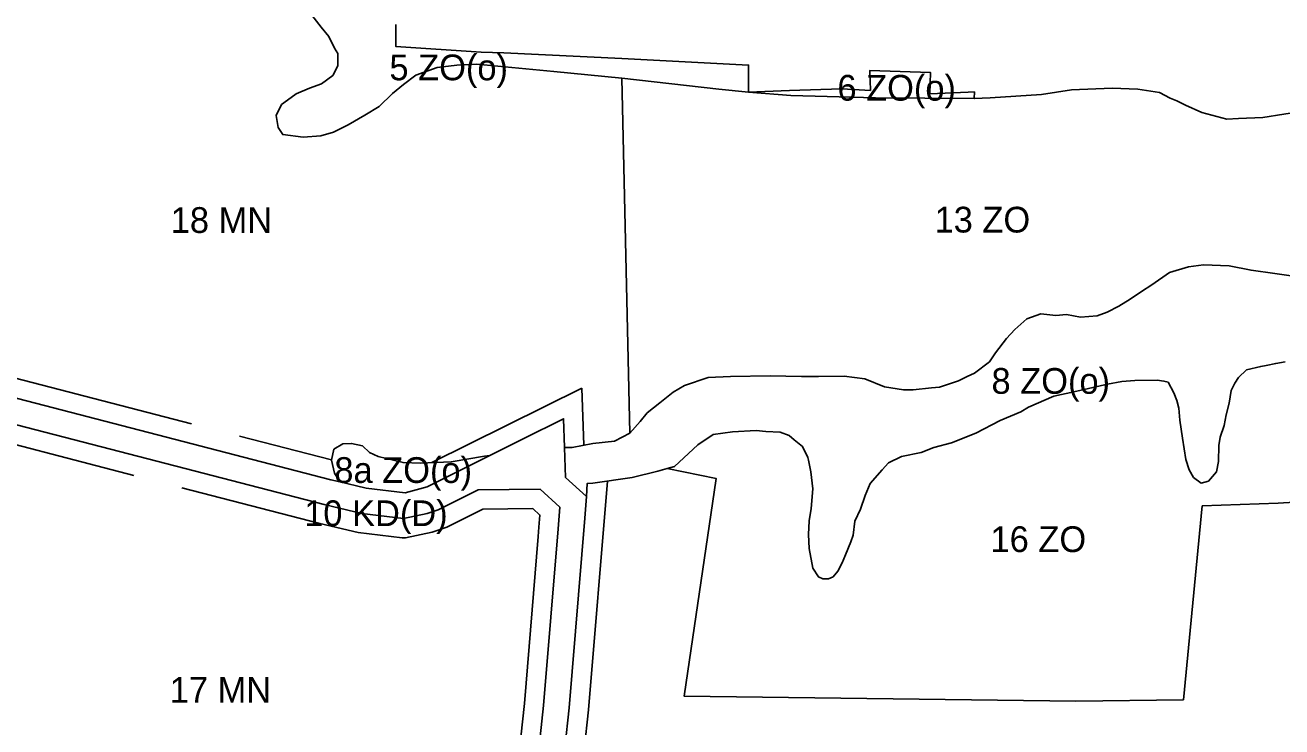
# Model space of a CAD drawing. Extents: x 7418056 to 7420315, y 5537846 to 5539505.
# Drawn here: x 7419326.3 to 7419814.6, y 5538625.8 to 5538898.4 of the extents above; entities that cross this region are included whole.
import ezdxf

# ---------------------------------------------------------------- set-up
doc = ezdxf.new("R2010")
doc.units = 0
for name, color, linetype in [('linie_rozgraniczajace', 7, 'Continuous'), ('linie_zabudowy_nieprzekraczalne', 7, 'Continuous'), ('oznaczenia_przeznaczen', 7, 'Continuous')]:
    doc.layers.add(name, color=color, linetype=linetype)

msp = doc.modelspace()

# ---------------------------------------------------------------- linework, layer by layer
at = {"layer": 'linie_rozgraniczajace'}
for points in [[(7419435.41, 5538905.24), (7419441.34, 5538897.54), (7419444.29, 5538893.92), (7419446.58, 5538889.34), (7419447.86, 5538887.27), (7419447.85, 5538882.53), (7419445.84, 5538878.78), (7419441.44, 5538875.59), (7419436.77, 5538873.9), (7419431.63, 5538871.68), (7419428.22, 5538869.21), (7419425.96, 5538867.48), (7419423.84, 5538863.25), (7419424.68, 5538858.55), (7419426.43, 5538855.82), (7419434.31, 5538854.85), (7419441.18, 5538855.33), (7419446.09, 5538856.82), (7419451.79, 5538859.64), (7419458.32, 5538863.36), (7419463.87, 5538866.68), (7419469.04, 5538871.8), (7419473.34, 5538875.24), (7419478.09, 5538878.94), (7419486.4, 5538881.85), (7419494.11, 5538882.81), (7419501.82, 5538883.13), (7419531.77, 5538880.4), (7419558.13, 5538877.75), (7419561.27, 5538739.79), (7419555.26, 5538736.69), (7419546.94, 5538735.83), (7419538.84, 5538734.29), (7419535.92, 5538734.26), (7419535.54, 5538745.43), (7419519.86, 5538737.62), (7419506.87, 5538731.17), (7419504.79, 5538730.89), (7419491.89, 5538728.69), (7419479.76, 5538728.2), (7419473.2, 5538728.4), (7419463.51, 5538730.81), (7419460.18, 5538732.31), (7419457.41, 5538734.97), (7419453.2, 5538735.84), (7419449.73, 5538735.7), (7419446.34, 5538733.62), (7419445.34, 5538729.38), (7419446.48, 5538724.28), (7419447.98, 5538722.01), (7419448.08, 5538721.04), (7419445.05, 5538721.75), (7419299.76, 5538759.34)], [(7419470.33, 5538898.55), (7419470.4, 5538890.01), (7419503.49, 5538887.91), (7419512.32, 5538887.58), (7419558.18, 5538885.41), (7419607.4, 5538882.82), (7419607.39, 5538872.31), (7419595.87, 5538873.47), (7419558.13, 5538877.75), (7419531.77, 5538880.4), (7419501.82, 5538883.13), (7419494.11, 5538882.81), (7419486.4, 5538881.85), (7419478.09, 5538878.94), (7419473.34, 5538875.24), (7419469.04, 5538871.8), (7419463.87, 5538866.68), (7419458.32, 5538863.36), (7419451.79, 5538859.64), (7419446.09, 5538856.82), (7419441.18, 5538855.33), (7419434.31, 5538854.85), (7419426.43, 5538855.82), (7419424.68, 5538858.55), (7419423.84, 5538863.25), (7419425.96, 5538867.48), (7419428.22, 5538869.21), (7419431.63, 5538871.68), (7419436.77, 5538873.9), (7419441.44, 5538875.59), (7419445.84, 5538878.78), (7419447.85, 5538882.53), (7419447.86, 5538887.27), (7419446.58, 5538889.34), (7419444.29, 5538893.92), (7419441.34, 5538897.54), (7419435.41, 5538905.24)], [(7419820.03, 5538800.76), (7419811.8, 5538801.83), (7419802.63, 5538803.1), (7419794.05, 5538804.8), (7419784.13, 5538805.26), (7419778.25, 5538804.5), (7419770.87, 5538802.29), (7419764.11, 5538797.5), (7419760.05, 5538794.9), (7419755.65, 5538791.95), (7419751.25, 5538789.17), (7419746.77, 5538786.8), (7419742.89, 5538785.36), (7419736.3, 5538784.91), (7419730.92, 5538785.91), (7419726.72, 5538785.51), (7419720.96, 5538786.2), (7419715.47, 5538784.25), (7419710.78, 5538780.06), (7419707.61, 5538776.63), (7419703.33, 5538771.07), (7419700.99, 5538767.61), (7419695.13, 5538763.2), (7419692.37, 5538761.92), (7419688.94, 5538760.15), (7419681.55, 5538757.74), (7419678.52, 5538757.39), (7419671.31, 5538756.62), (7419667.56, 5538756.71), (7419660.27, 5538757.82), (7419652.52, 5538760.97), (7419644.48, 5538762.04), (7419634.59, 5538761.81), (7419627.98, 5538761.89), (7419615.8, 5538762.1), (7419600.35, 5538761.81), (7419591.68, 5538761.46), (7419582.48, 5538758.34), (7419578.14, 5538755.83), (7419572.96, 5538751.67), (7419567.94, 5538747.7), (7419565.27, 5538744.33), (7419561.27, 5538739.79), (7419558.13, 5538877.75), (7419595.87, 5538873.47), (7419607.39, 5538872.31), (7419607.4, 5538872.31), (7419623.8, 5538871.02), (7419656.72, 5538870.12), (7419695.08, 5538869.84), (7419701.24, 5538870.09), (7419721.14, 5538871.44), (7419732.86, 5538873.18), (7419748.61, 5538873.82), (7419758.59, 5538873.53), (7419766.99, 5538872.21), (7419771.25, 5538870.03), (7419773.81, 5538868.91), (7419777.11, 5538867.31), (7419783.53, 5538864.42), (7419793.16, 5538861.82), (7419797.76, 5538862.07), (7419807.13, 5538862.49), (7419823.48, 5538865.05)], [(7419536.32, 5538722.59), (7419535.92, 5538734.26), (7419538.84, 5538734.29), (7419546.94, 5538735.83), (7419555.26, 5538736.69), (7419561.27, 5538739.79), (7419565.27, 5538744.33), (7419567.94, 5538747.7), (7419572.96, 5538751.67), (7419578.14, 5538755.83), (7419582.48, 5538758.34), (7419591.68, 5538761.46), (7419600.35, 5538761.81), (7419615.8, 5538762.1), (7419627.98, 5538761.89), (7419634.59, 5538761.81), (7419644.48, 5538762.04), (7419652.52, 5538760.97), (7419660.27, 5538757.82), (7419667.56, 5538756.71), (7419671.31, 5538756.62), (7419678.52, 5538757.39), (7419681.55, 5538757.74), (7419688.94, 5538760.15), (7419692.37, 5538761.92), (7419695.13, 5538763.2), (7419700.99, 5538767.61), (7419703.33, 5538771.07), (7419707.61, 5538776.63), (7419710.78, 5538780.06), (7419715.47, 5538784.25), (7419720.96, 5538786.2), (7419726.72, 5538785.51), (7419730.92, 5538785.91), (7419736.3, 5538784.91), (7419742.89, 5538785.36), (7419746.77, 5538786.8), (7419751.25, 5538789.17), (7419755.65, 5538791.95), (7419760.05, 5538794.9), (7419764.11, 5538797.5), (7419770.87, 5538802.29), (7419778.25, 5538804.5), (7419784.13, 5538805.26), (7419794.05, 5538804.8), (7419802.63, 5538803.1), (7419811.8, 5538801.83), (7419820.03, 5538800.76)], [(7419870.81, 5538716.16), (7419813.18, 5538712.6), (7419783.62, 5538711.58), (7419776.36, 5538636.3), (7419734.58, 5538635.75), (7419582.32, 5538637.71), (7419594.85, 5538722.21), (7419575.72, 5538726.07), (7419578.66, 5538726.9), (7419587.7, 5538735.25), (7419593.62, 5538739.31), (7419601.22, 5538740.32), (7419610.41, 5538740.86), (7419614.08, 5538740.49), (7419619.65, 5538740.2), (7419623.18, 5538738.95), (7419625.16, 5538737.3), (7419628.36, 5538734.69), (7419630.41, 5538730.33), (7419630.68, 5538729.41), (7419631.57, 5538724.78), (7419632.3, 5538718.26), (7419631.68, 5538710.53), (7419630.94, 5538705.83), (7419630.68, 5538700.44), (7419630.9, 5538695.08), (7419632.38, 5538687.43), (7419634.62, 5538684.01), (7419636.3, 5538683.2), (7419638.4, 5538683.23), (7419640.24, 5538684.01), (7419642.09, 5538686.2), (7419643.76, 5538689.52), (7419645.03, 5538692.61), (7419647.17, 5538697.61), (7419648, 5538700.21), (7419648.71, 5538705.61), (7419650.86, 5538710.37), (7419652.75, 5538715.59), (7419654.67, 5538720.34), (7419659.35, 5538725.66), (7419661.82, 5538728.34), (7419666.86, 5538730.79), (7419674.45, 5538732.32), (7419679.41, 5538734.25), (7419686.28, 5538736.09), (7419695.69, 5538739.78), (7419705.11, 5538744.82), (7419713.15, 5538748.18), (7419716.12, 5538749.94), (7419726.04, 5538754.21), (7419733.78, 5538755.91), (7419746.8, 5538758.94), (7419752.38, 5538759.86), (7419757.5, 5538760.3), (7419766.16, 5538760.42), (7419768.74, 5538760.06), (7419770.39, 5538759.66), (7419772.66, 5538755.54), (7419773.72, 5538752.55), (7419774.54, 5538749.55), (7419774.96, 5538744.89), (7419775.95, 5538737.92), (7419777.23, 5538729.56), (7419778.56, 5538725.65), (7419780.31, 5538722.68), (7419783.21, 5538720.46), (7419786.04, 5538721.22), (7419789.2, 5538724.82), (7419789.91, 5538728.85), (7419790.1, 5538735), (7419790.66, 5538738.28), (7419792.12, 5538742.78), (7419792.88, 5538747.02), (7419794.1, 5538751.51), (7419794.84, 5538756.44), (7419796.36, 5538759.31), (7419797.68, 5538761.46), (7419800.83, 5538764.39), (7419806.38, 5538765.79), (7419808.48, 5538766.12), (7419812.18, 5538766.97), (7419815.9, 5538767.58)], [(7419815.9, 5538767.58), (7419812.18, 5538766.97), (7419808.48, 5538766.12), (7419806.38, 5538765.79), (7419800.83, 5538764.39), (7419797.68, 5538761.46), (7419796.36, 5538759.31), (7419794.84, 5538756.44), (7419794.1, 5538751.51), (7419792.88, 5538747.02), (7419792.12, 5538742.78), (7419790.66, 5538738.28), (7419790.1, 5538735), (7419789.91, 5538728.85), (7419789.2, 5538724.82), (7419786.04, 5538721.22), (7419783.21, 5538720.46), (7419780.31, 5538722.68), (7419778.56, 5538725.65), (7419777.23, 5538729.56), (7419775.95, 5538737.92), (7419774.96, 5538744.89), (7419774.54, 5538749.55), (7419773.72, 5538752.55), (7419772.66, 5538755.54), (7419770.39, 5538759.66), (7419768.74, 5538760.06), (7419766.16, 5538760.42), (7419757.5, 5538760.3), (7419752.38, 5538759.86), (7419746.8, 5538758.94), (7419733.78, 5538755.91), (7419726.04, 5538754.21), (7419716.12, 5538749.94), (7419713.15, 5538748.18), (7419705.11, 5538744.82)], [(7419299.76, 5538759.34), (7419445.05, 5538721.75), (7419448.08, 5538721.04), (7419458.86, 5538718.51), (7419474.03, 5538716.65), (7419482.48, 5538719.05), (7419506.87, 5538731.17), (7419519.86, 5538737.62), (7419535.54, 5538745.43), (7419535.92, 5538734.26), (7419536.32, 5538722.59), (7419544.39, 5538715.22), (7419543.82, 5538706.76), (7419537.73, 5538633.12), (7419531.03, 5538570.98)], [(7419297.9, 5538749.52), (7419442.55, 5538712.07), (7419445.79, 5538711.3), (7419457.11, 5538708.65), (7419473.33, 5538706.66), (7419482.55, 5538708.68), (7419486.79, 5538710.03), (7419502.41, 5538717.79), (7419526.45, 5538718.07), (7419534.1, 5538711.07), (7419533.42, 5538702.73), (7419527.79, 5538634.11), (7419521.09, 5538572.08)], [(7419521.09, 5538572.08), (7419527.79, 5538634.11), (7419533.42, 5538702.73), (7419534.1, 5538711.07), (7419526.45, 5538718.07), (7419502.41, 5538717.79), (7419486.79, 5538710.03), (7419482.55, 5538708.68), (7419473.33, 5538706.66), (7419457.11, 5538708.65), (7419445.79, 5538711.3), (7419442.55, 5538712.07), (7419297.9, 5538749.52)], [(7419705.11, 5538744.82), (7419695.69, 5538739.78), (7419686.28, 5538736.09), (7419679.41, 5538734.25), (7419674.45, 5538732.32), (7419666.86, 5538730.79), (7419661.82, 5538728.34), (7419659.35, 5538725.66), (7419654.67, 5538720.34), (7419652.75, 5538715.59), (7419650.86, 5538710.37), (7419648.71, 5538705.61), (7419648, 5538700.21), (7419647.17, 5538697.61), (7419645.03, 5538692.61), (7419643.76, 5538689.52), (7419642.09, 5538686.2), (7419640.24, 5538684.01), (7419638.4, 5538683.23), (7419636.3, 5538683.2), (7419634.62, 5538684.01), (7419632.38, 5538687.43), (7419630.9, 5538695.08), (7419630.68, 5538700.44), (7419630.94, 5538705.83), (7419631.68, 5538710.53), (7419632.3, 5538718.26), (7419631.57, 5538724.78), (7419630.68, 5538729.41), (7419630.41, 5538730.33), (7419628.36, 5538734.69), (7419625.16, 5538737.3), (7419623.18, 5538738.95), (7419619.65, 5538740.2), (7419614.08, 5538740.49), (7419610.41, 5538740.86), (7419601.22, 5538740.32), (7419593.62, 5538739.31), (7419587.7, 5538735.25), (7419578.66, 5538726.9), (7419575.72, 5538726.07), (7419572.13, 5538725.07), (7419562.15, 5538722.58), (7419546.88, 5538720.38), (7419544.73, 5538720.32), (7419544.39, 5538715.22), (7419536.32, 5538722.59)], [(7419531.03, 5538570.98), (7419537.73, 5538633.12), (7419543.82, 5538706.76), (7419544.39, 5538715.22), (7419544.73, 5538720.32), (7419546.88, 5538720.38), (7419562.15, 5538722.58), (7419572.13, 5538725.07), (7419575.72, 5538726.07), (7419594.85, 5538722.21), (7419582.32, 5538637.71), (7419734.58, 5538635.75), (7419776.36, 5538636.3), (7419783.62, 5538711.58), (7419813.18, 5538712.6), (7419870.81, 5538716.16)]]:
    msp.add_lwpolyline(points, dxfattribs=at)
for points in [[(7419607.4, 5538872.31), (7419623.36, 5538872.96), (7419643.68, 5538873.61), (7419654.76, 5538872.98), (7419654.55, 5538880.79), (7419678.1, 5538879.93), (7419677.85, 5538871.7), (7419692.69, 5538872.28), (7419695.16, 5538872.38), (7419695.08, 5538869.84), (7419656.72, 5538870.12), (7419623.8, 5538871.02)], [(7419445.34, 5538729.38), (7419446.34, 5538733.62), (7419449.73, 5538735.7), (7419453.2, 5538735.84), (7419457.41, 5538734.97), (7419460.18, 5538732.31), (7419463.51, 5538730.81), (7419473.2, 5538728.4), (7419479.76, 5538728.2), (7419491.89, 5538728.69), (7419504.79, 5538730.89), (7419506.87, 5538731.17), (7419482.48, 5538719.05), (7419474.03, 5538716.65), (7419458.86, 5538718.51), (7419448.08, 5538721.04), (7419447.98, 5538722.01), (7419446.48, 5538724.28)]]:
    msp.add_lwpolyline(points, close=True, dxfattribs=at)
at = {"layer": 'linie_zabudowy_nieprzekraczalne'}
for points in [[(7419230.05, 5538863.26), (7419226.83, 5538855.99), (7419228.66, 5538847.95), (7419243.08, 5538793.44), (7419247.97, 5538777.43), (7419252.45, 5538775.08), (7419263.51, 5538774.25), (7419286.23, 5538769.54), (7419301.46, 5538766.66), (7419390.96, 5538743.5)], [(7419542.63, 5538757.31), (7419484.41, 5538728.39)], [(7419542.63, 5538757.31), (7419543.39, 5538735.16)], [(7419368.6, 5538723.46), (7419296, 5538742.25), (7419281.37, 5538745.02), (7419260.02, 5538749.44), (7419256.85, 5538749.68), (7419257.12, 5538748.86), (7419282.73, 5538674.66), (7419292.85, 5538641.96), (7419299.13, 5538616.52), (7419304.54, 5538592.72), (7419306.11, 5538586.92), (7419308.15, 5538582.33), (7419309.58, 5538580.3), (7419312.51, 5538577.96), (7419316.49, 5538575.34), (7419323.33, 5538572.13), (7419324.73, 5538571.63)], [(7419409.57, 5538738.68), (7419445.35, 5538729.42)], [(7419552.54, 5538721.2), (7419545.2, 5538632.41), (7419538.48, 5538570.17), (7419535.81, 5538546.23)], [(7419474.08, 5538699.15), (7419472.8, 5538699.17), (7419455.79, 5538701.26), (7419440.8, 5538704.78), (7419387.2, 5538718.65)], [(7419513.63, 5538572.9), (7419520.31, 5538634.78), (7419525.68, 5538699.64), (7419525.94, 5538703.34), (7419526.33, 5538708.03), (7419523.57, 5538710.54), (7419504.21, 5538710.31), (7419490.13, 5538703.32), (7419484.49, 5538701.43), (7419474.08, 5538699.15)]]:
    msp.add_lwpolyline(points, dxfattribs=at)

# ---------------------------------------------------------------- texts
at = {"layer": 'oznaczenia_przeznaczen'}
for s, p in [('5 ZO(o)', (7419467.87, 5538876.93)), ('6 ZO(o)', (7419641.9, 5538869.02)), ('18 MN', (7419382.92, 5538817.63)), ('13 ZO', (7419679.65, 5538817.79)), ('8 ZO(o)', (7419701.77, 5538755.14)), ('8a ZO(o)', (7419446.47, 5538720.51)), ('10 KD(D)', (7419434.77, 5538703.74)), ('16 ZO', (7419701.39, 5538693.66)), ('17 MN', (7419382.53, 5538635.13))]:
    msp.add_text(s, height=10, dxfattribs=at).set_placement(p)

doc.saveas('drawing.dxf')
